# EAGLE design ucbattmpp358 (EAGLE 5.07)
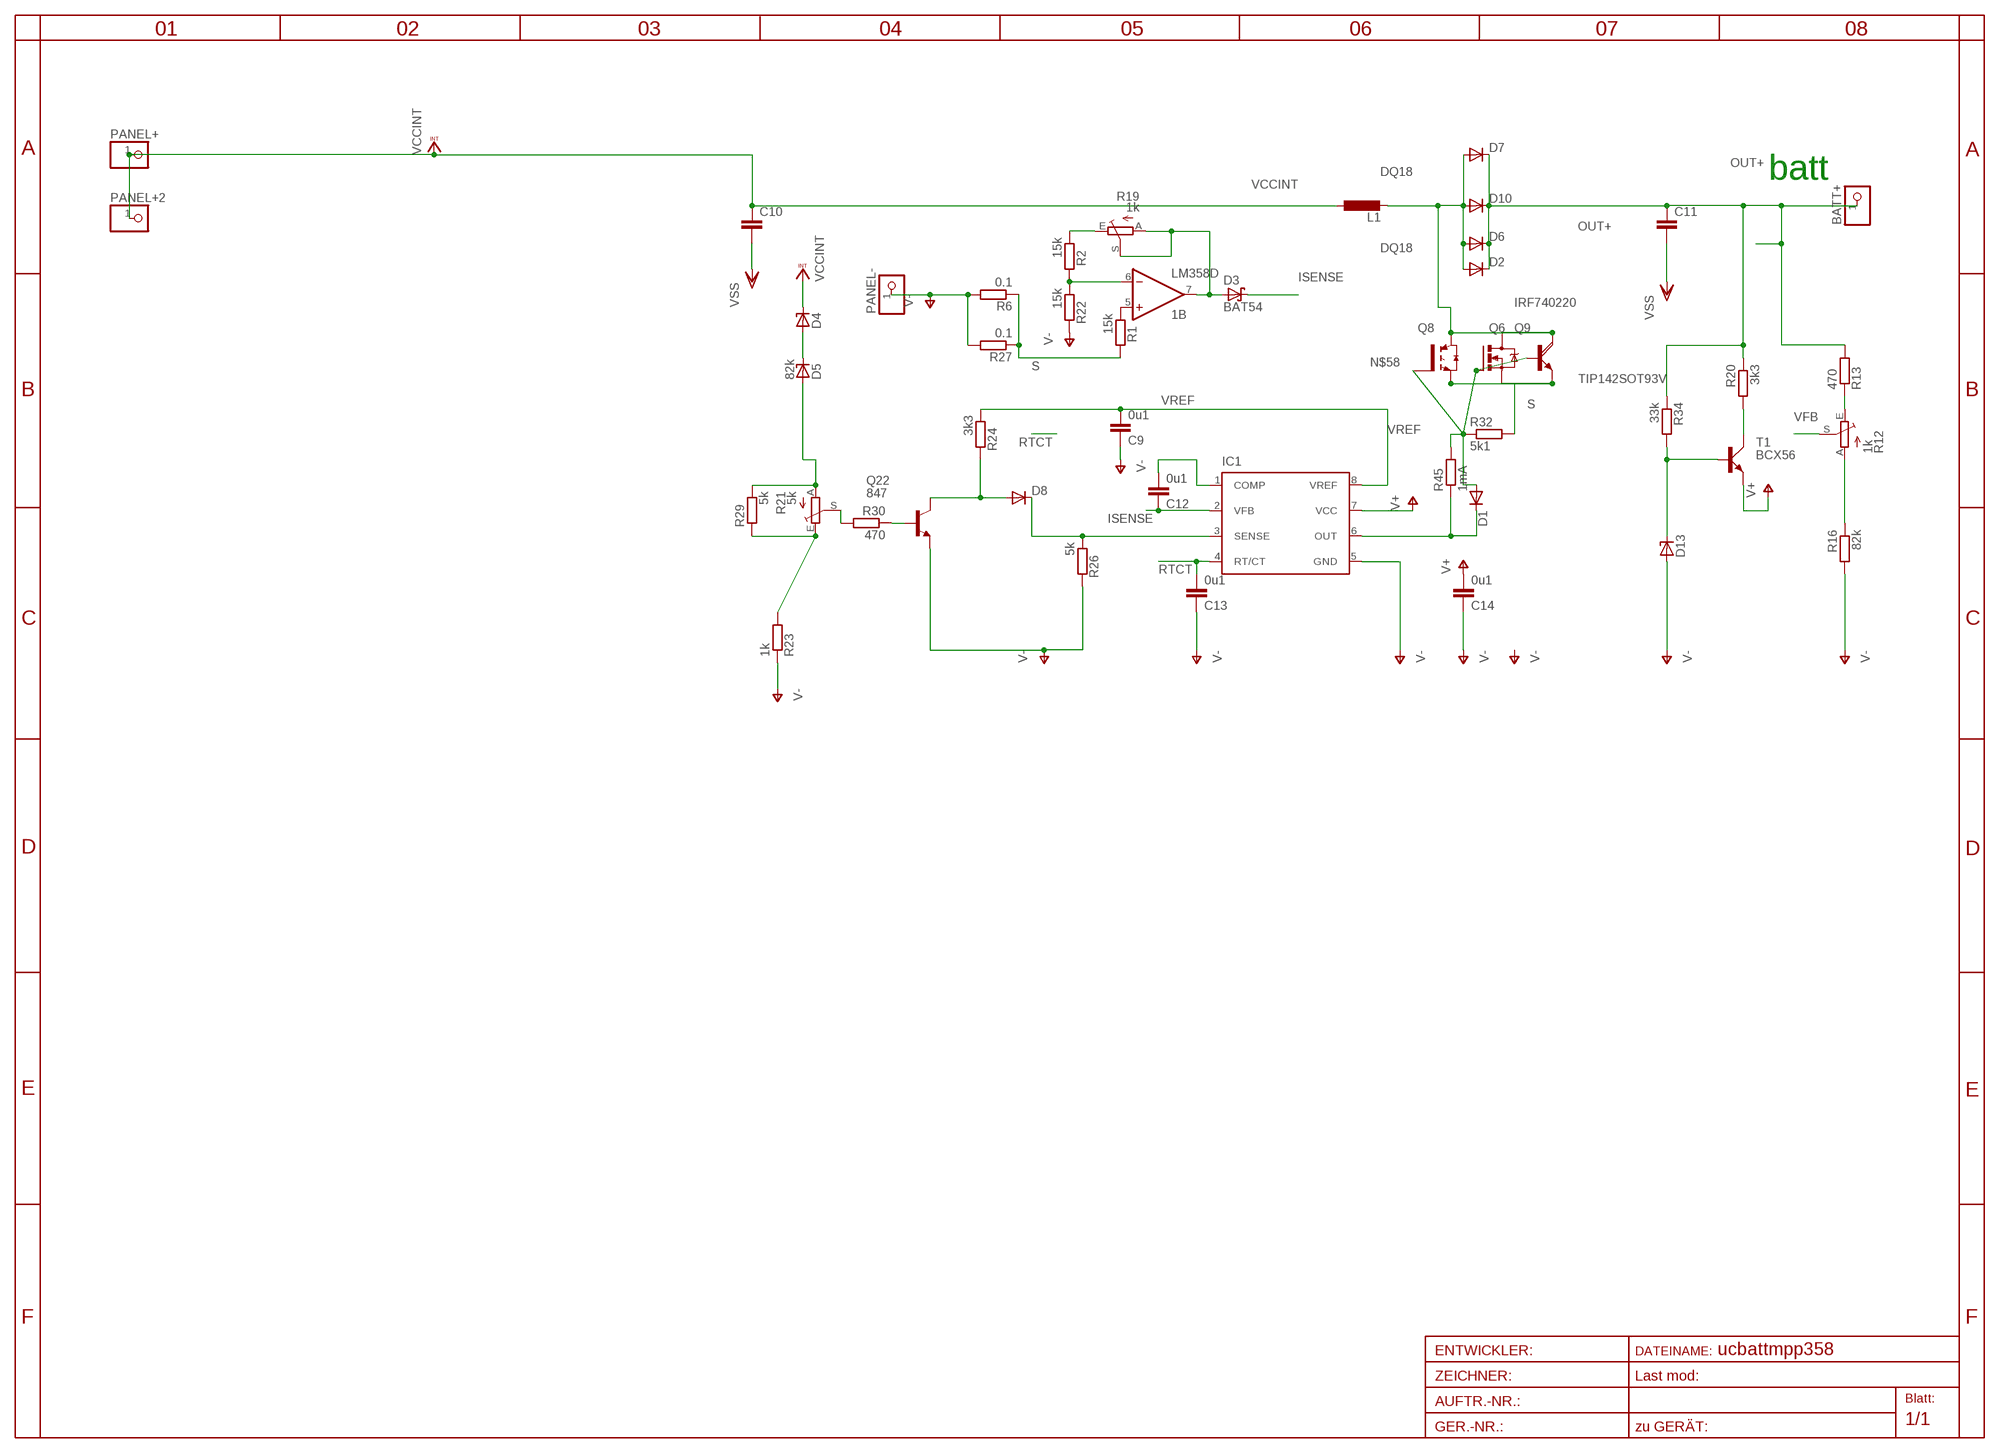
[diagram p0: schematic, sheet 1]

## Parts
1  LM358D  [SO08]
BATT+  PINHD-1X12MM3  [1X2MM3]
C9  0u1  C-EUC1206  [C1206]
C10  C-EU075-052X106  [C075-052X106]
C11  C-EU075-052X106  [C075-052X106]
C12  0u1  C-EUC0805  [C0805]
C13  0u1  C-EUC1206  [C1206]
C14  0u1  C-EUC1206  [C1206]
D1  DIODE-MINIMELF  [MINIMELF]
D2  DIODE-SMC  [SMC]
D3  BAT54  [SOT23]
D4  ZENER-DIODESOD80C  [SOD80C]
D5  82k  ZENER-DIODESOD80C  [SOD80C]
D6  DIODE-SMC  [SMC]
D7  DIODE-SMC  [SMC]
D8  DIODE-MINIMELF  [MINIMELF]
D10  DIODE-SMC  [SMC]
D13  ZENER-DIODESOD80C  [SOD80C]
IC1  UC1843D8  [SO-08]
L1  L-EUOPEN6  [OPEN6_3]
PANEL+  PINHD-1X11MM6  [1X1MM8]
PANEL+2  PINHD-1X12MM3  [1X2MM3]
PANEL-  PINHD-1X12MM3  [1X2MM3]
Q6  IRF740220  [TO220BV]
Q8  IRG4BC15UD-S  [D2PACK]
Q9  TIP142SOT93V  [SOT93V]
Q22  847  BC847ASMD  [SOT23]
R1  15k  R-EU_R0805  [R0805]
R2  15k  R-EU_R0805  [R0805]
R6  0.1  R-EU_0207/10  [0207/10]
R12  1k  TRIM_EU-S64W  [S64W]
R13  470  R-EU_R0805  [R0805]
R16  82k  R-EU_R0805  [R0805]
R19  1k  TRIM_EU-S64W  [S64W]
R20  3k3  R-EU_R0805  [R0805]
R21  5k  TRIM_EU-S64W  [S64W]
R22  15k  R-EU_R0805  [R0805]
R23  1k  R-EU_R0805  [R0805]
R24  3k3  R-EU_R0805  [R0805]
R26  5k  R-EU_R0805  [R0805]
R27  0.1  R-EU_R3216  [R3216]
R29  5k  R-EU_R0805  [R0805]
R30  470  R-EU_R0805  [R0805]
R32  5k1  R-EU_R0805  [R0805]
R34  33k  R-EU_R0805  [R0805]
R45  1mA  R-EU_R0805  [R0805]
T1  BCX56  [SOT223]

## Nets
DQ18: D2.A D6.A D7.A D10.A L1.2 Q6.D Q8.2(C) Q9.C
ISENSE: D3.3(C) D8.C IC1.3(SENSE) R26.1
N$1: 1.5(B:+IN) R1.1
N$2: R2.1 R19.E
N$3: Q22.1(B) R30.1
N$18: C12.2 IC1.1(COMP)
N$21: R12.A R16.1
N$22: 1.7(B:OUT) D3.1(A) R19.A R19.S
N$23: R20.2 T1.2(C)
N$25: D1.C IC1.6(OUT) R45.1
N$26: D13.C R34.2 T1.1(B)
N$27: 1.6(B:-IN) R2.2 R22.1
N$30: D4.A D5.C
N$32: D5.A R21.A R29.1
N$34: R21.E R23.2 R29.2
N$37: R12.E R13.1
N$58: D1.A Q6.G Q8.1(G) Q9.B R32.1 R45.2
N$71: D8.A Q22.3(C) R24.2
OUT+: BATT+.1 C11.1 D2.C D6.C D7.C D10.C R13.2 R20.1 R34.1
PRB1: R21.S R30.2
RTCT: C13.2 IC1.4(RT/CT)
S: Q6.S Q8.3(E) Q9.E R1.2 R6.1 R27.1 R32.2
V+: C14.2 IC1.7(VCC) T1.3(E)
V-: C9.1 C10.2 C11.2 C13.1 C14.1 D13.A IC1.5(GND) PANEL-.1 Q22.2(E) R6.2 R16.2 R22.2 R23.1 R26.2 R27.2 ; supply symbol labelled VSS
VCCINT: C10.1 D4.C L1.1 PANEL+2.1 PANEL+.1
VFB: C12.1 IC1.2(VFB) R12.S
VREF: C9.2 IC1.8(VREF) R24.1
Unconnected: 1.1(A:OUT) 1.2(A:-IN) 1.3(A:+IN)

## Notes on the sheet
- batt

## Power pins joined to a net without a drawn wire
V+: 1.8(P:V+)
V-: 1.4(P:V-)

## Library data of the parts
1 = linear:LM358: OP AMP also LM158; LM258; LM2904 Source: http://cache.national.com/ds/LM/LM158.pdf
BATT+ PANEL+ PANEL+2 PANEL- = pinhead:PINHD-1X1: PIN HEADER
C9-C14 = rcl:C-EU: CAPACITOR, European symbol
D1 D2 D6-D8 D10 = diode:DIODE-: DIODE
D3 = diode:BAT54: Schottky Diodes
D4 D5 D13 = diode:ZENER-DIODE: Z-Diode
IC1 = texas:UC1843D8: PULSE WIDTH MODULATOR
L1 = rcl:L-EU: INDUCTOR, European symbol
Q6 = transistor-power:IRF740: N-CHANNEL MOS FET
Q8 = transistor-power:IRG4BC15UD-: INSULATED GATE BIPOLAR TRANSISTOR WITH ULTRAFAST SOFT RECOVERY DIODE
Q9 = transistor-power:TIP142: NPN DARLINGTON TRANSISTOR
Q22 = transistor-npn:BC847*: NPN Transistor
R1 R2 R6 R13 R16 R20 R22-R24 R26 R27 R29 R30 R34 = rcl:R-EU_: RESISTOR, European symbol
R12 R19 R21 = pot:TRIM_EU-: POTENTIOMETER
R32 R45 = rcl-2:R-EU_: RESISTOR, European symbol
T1 = transistor-power:BCX56

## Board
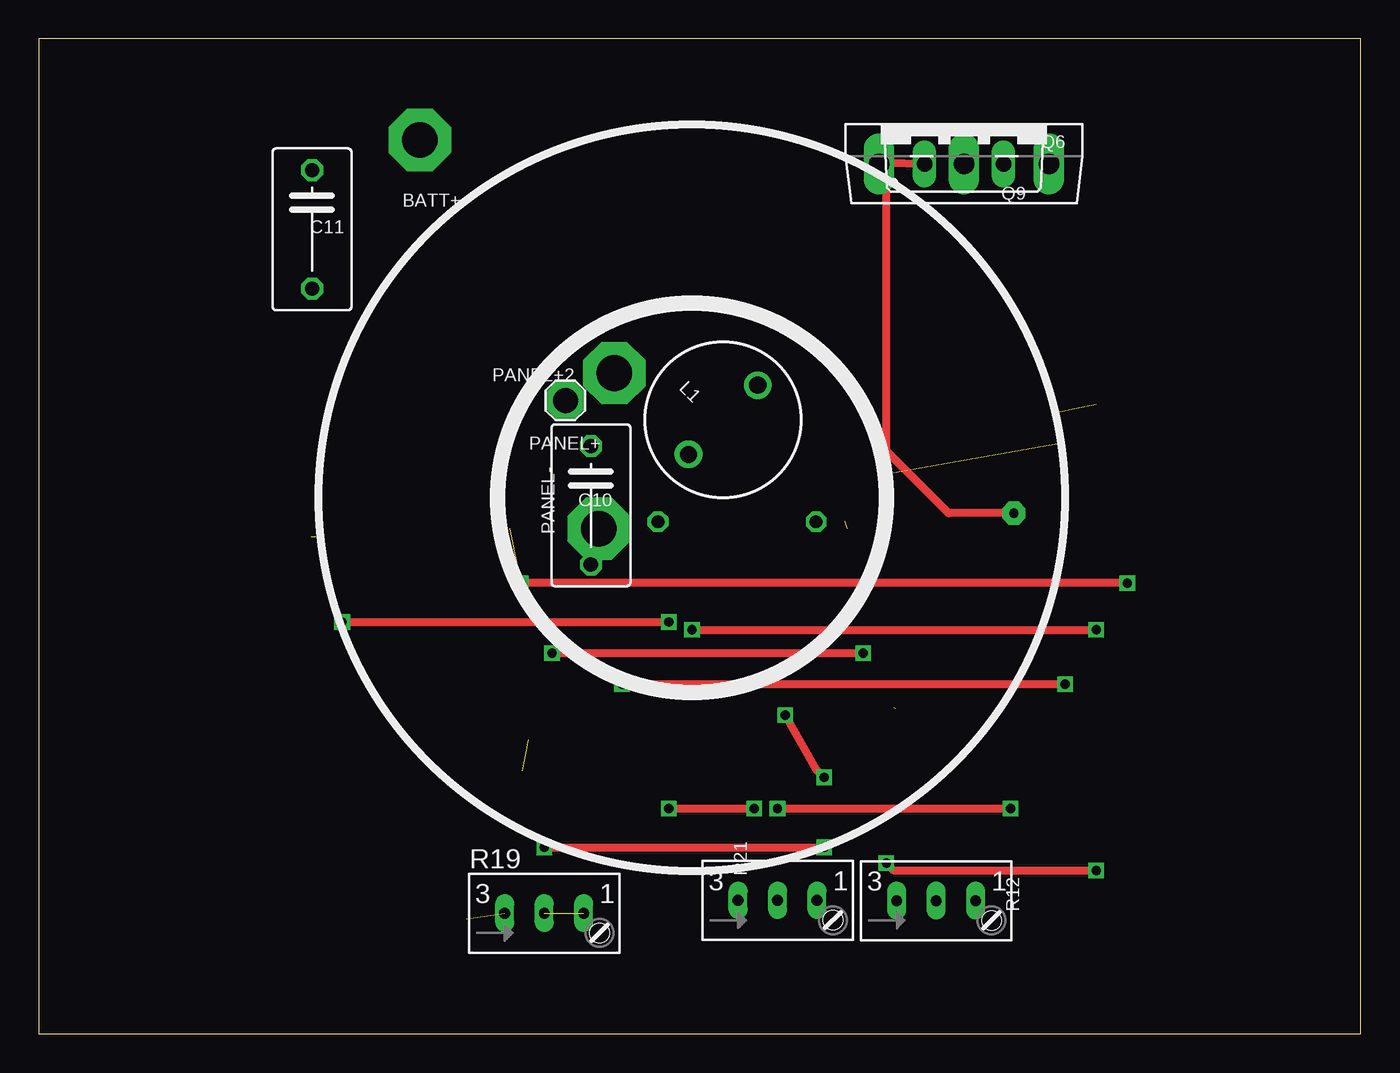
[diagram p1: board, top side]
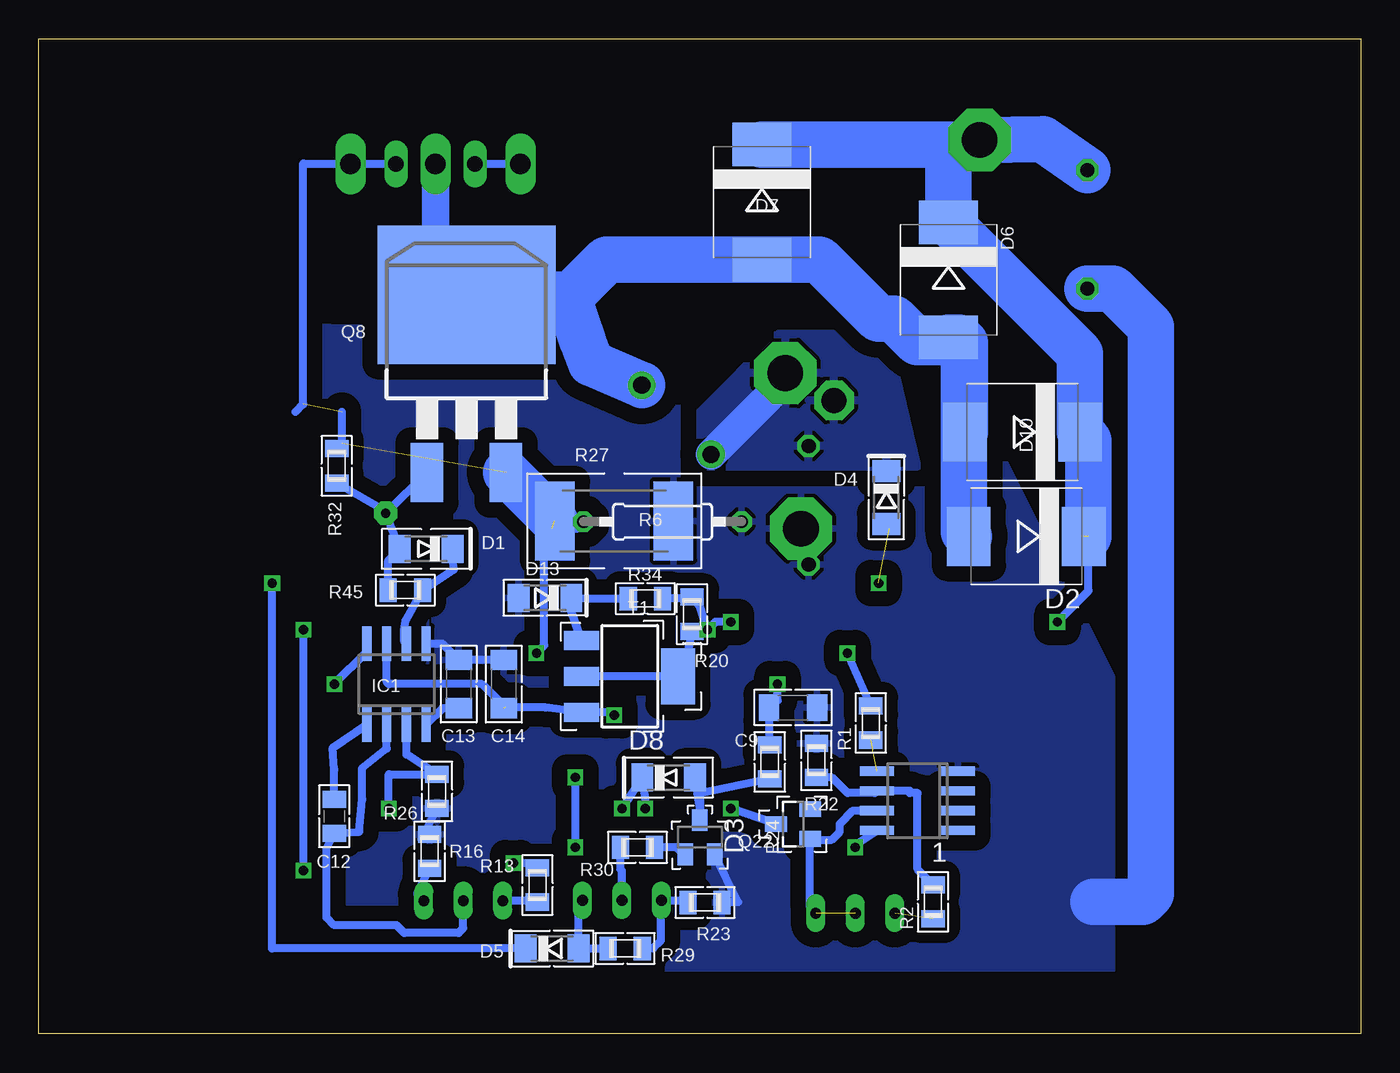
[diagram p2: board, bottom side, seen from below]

Size 85 x 64 mm. Coordinates in mm from the lower left corner, seen from the top.
Outline: 0,0 85,0 85,64 0,64 0,0
Copper layers (1*16): Top 0.035mm / dielectric 1.5mm / Bottom 0.035mm
Design rules "default *": minimum track width 10mil, minimum drill 24mil, track to track 8mil, track to pad 8mil, pad to pad 8mil, via to via 8mil, smd to smd 8mil, copper to edge 4mm, drill to drill 8mil, minimum pad ring 10mil, minimum via ring 8mil, stop-mask expansion 4mil, vias tented up to drill 0mil, thermal gap 10mil

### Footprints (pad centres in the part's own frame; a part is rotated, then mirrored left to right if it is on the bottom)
SO08 = smd 0.6 x 2.2: 1 -1.905,-2.6; 2 -0.635,-2.6; 3 0.635,-2.6; 4 1.905,-2.6; 5 1.905,2.6; 6 0.635,2.6; 7 -0.635,2.6; 8 -1.905,2.6
1X2MM3 = drill 2.3 pad 4 octagon: 1 0,0
C1206 = smd 1.3 x 1.7: 1 -1.55,0; 2 1.55,0
C075-052X106 = drill 0.914 octagon: 1 -3.81,0; 2 3.81,0
C0805 = smd 1.1 x 1.5: 1 -1.1,0; 2 1.1,0
MINIMELF = smd 1.4 x 1.8: A 1.7,0; C -1.7,0
SMC = smd 2.8 x 3.8: A 3.7,0; C -3.7,0
SOT23 = smd 1 x 1.4: 1 -0.95,-1.1; 2 0.95,-1.1; 3 0,1.1
SOD80C = smd 1.4 x 1.8: A 1.7,0; C -1.7,0
SO-08 = smd 0.6 x 2.2: 1 -1.905,-2.6; 2 -0.635,-2.6; 3 0.635,-2.6; 4 1.905,-2.6; 5 1.905,2.6; 6 0.635,2.6; 7 -0.635,2.6; 8 -1.905,2.6
OPEN6_3 = drill 1.1 pad 1.778 round: 1 -3.15,0; 2 3.15,0
1X1MM8 = drill 1.6 pad 2.54 octagon: 1 0,0
TO220BV = drill 1.016 long: D 0,-2.54; G -2.54,-2.54; S 2.54,-2.54
D2PACK = smd 2.083 x 3.81: 1 -2.54,-8.89; 3 2.54,-8.89 | smd 11.43 x 8.89: 2 0,2.54
SOT93V = drill 1.3 pad 1.676 long: B -5.461,-2.54; C 0,-2.54; E 5.461,-2.54
R0805 = smd 1.1 x 1.5: 1 -1.1,0; 2 1.1,0
0207/10 = drill 0.813 octagon: 1 -5.08,0; 2 5.08,0
S64W = drill 0.7 long: A 2.54,1.27; E -2.54,1.27; S 0,1.27
R3216 = smd 2.54 x 5.08: 1 -3.81,0; 2 3.81,0
SOT223 = smd 1.219 x 2.235: 1 -2.311,-3.099; 2 0,-3.099; 3 2.311,-3.099 | smd 3.6 x 2.2: 4 0,3.099

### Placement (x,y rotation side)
1  28.5,15 90 bottom
BATT+  24.5,57.5 0 top
C9  36.5,21 180 bottom
C10  35.5,34 270 top
C11  17.57,51.75 270 top
C12  66,14 90 bottom
C13  58,22.5 270 bottom
C14  55.1,22.5 270 bottom
D1  60.1,31.2 180 bottom
D2  21.5,32 180 bottom
D3  36.5,13.5 90 bottom
D4  30.5,34.5 270 bottom
D5  52,5.5 0 bottom
D6  26.5,48.5 270 bottom
D7  38.5,53.5 270 bottom
D8  44.5,16.5 0 bottom
D10  21.75,38.71 180 bottom
D13  52.46,28.05 180 bottom
IC1  62,22.5 0 bottom
L1  44,39.5 45 top
PANEL+  33.86,40.74 0 top
PANEL+2  37,42.5 0 top
PANEL-  36,32.5 90 top
Q6  59.5,58.5 0 top
Q8  57.5,45 0 bottom
Q9  59.5,58.5 0 top
Q22  42.49,12.66 0 bottom
R1  31.5,20 90 bottom
R2  27.5,8.5 90 bottom
R6  44.9,32.95 0 bottom
R12  57.7,7.3 0 top
R13  52.94,9.58 90 bottom
R16  59.88,11.75 90 bottom
R19  32.5,6.5 0 top
R20  43,27 270 bottom
R21  47.51,7.32 0 top
R22  35,17.6 90 bottom
R23  42.16,8.46 180 bottom
R24  38,17.5 270 bottom
R26  59.4,15.6 270 bottom
R27  48,33 0 bottom
R29  47.3,5.5 0 bottom
R30  46.5,12 180 bottom
R32  65.84,36.55 90 bottom
R34  46,28 180 bottom
R45  61.43,28.55 180 bottom
T1  47,23 270 bottom

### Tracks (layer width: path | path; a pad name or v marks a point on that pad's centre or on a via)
DQ18
  Bottom 1.778: 59.5,48.04 Q9.C
  Bottom 2.54: Q8.2 59.5,48.04
  Bottom 3: Q8.2 51.04,47.54 50.97,47.34 | 50.97,47.34 50,44.5 49.5,43.15 L1.2 | 50.97,47.34 48.51,49.8 D7.A 34.8,49.8 31,46 30,46 28.5,44.5 26.8,44.5 D6.A 25.8,44.8 25.5,44.5 | 25.5,44.5 25.5,32.3 D2.A | D10.A 25.45,44.45 25.5,44.5
ISENSE  (via drill 0.6)
  Top 0.5: v47.5,14.5 v62.5,14.5 | v40.5,14.5 v46,14.5
  Bottom 0.5: IC1.3 61.37,17.96 R26.1 62.5,16.7 v62.5,14.5 | v47.5,14.5 D8.C 46,15.2 v46,14.5 | D3.3 v40.5,14.5
N$1  (1 unrouted)
N$2  (1 unrouted)
N$3
  Bottom 0.5: Q22.1 43.56,11.56 44,12 R30.1
N$18
  Bottom 0.5: IC1.1 66.1,18.4 66,17 C12.2
N$21
  Bottom 0.5: R12.A 60.67,9.01 R16.1
N$22  (1 unrouted)
  Bottom 0.5: R19.A 35.4,8.13 D3.1 35.35,12.5 34,12.5 33.5,13 33.5,13.5 32.63,14.37 1.7
N$23
  Bottom 0.5: T1.2 43.6,23 R20.2
N$25
  Bottom 0.5: IC1.6 61.5,25.23 61.5,26 61.43,26.57 R45.1 58.33,29.87 D1.C
N$26
  Bottom 0.5: R34.2 49.71,28 D13.C 50.76,27.15 T1.1
N$27
  Bottom 0.5: R2.2 28.5,10.6 28.5,15.5 29,15.5 29,15.63 1.6 31.23,15.5 33,15.5 34,16.5 R22.1
N$30  (via drill 0.6)  (1 unrouted)
  Top 0.5: v70,29 v31,29
  Bottom 0.5: D5.C 70,5.5 v70,29 | 30.3,32.5 D4.A
N$32
  Bottom 0.5: R29.1 D5.A 50.3,8.34 R21.A
N$34
  Bottom 0.5: R29.2 45.5,5.5 45,6 45,8.56 R21.E 43.4,8.59 R23.2
N$37
  Bottom 0.5: R13.1 53.03,8.57 R12.E
N$58  (via drill 0.6 pad 1.5)
  Top 0.5: Q6.G 54.46,56.04 54.5,53 54.5,37.5 58.5,33.5 v62.7,33.5
  Bottom 0.5: 62.59,33.55 R32.1 | 62.59,33.55 Q8.1 | Q6.G Q9.B | R45.2 62.53,30.43 D1.A v62.7,33.5 62.7,33.95 62.59,33.55
N$71
  Bottom 0.5: 42.49,14.5 Q22.3 | 42.49,14.5 42.49,15.46 R24.2 | 42.49,14.5 D8.A
OUT+  (via drill 0.6)  (1 unrouted)
  Top 0.5: v42,26 v68,26 | v68,10.5 55,10.5 v54.5,11 | v19.5,26.5 v40.5,26.5
  Bottom 0.5: R34.1 43,28 R20.1 42.5,27.5 v42,26 41.5,26.5 v40.5,26.5 | v68,26 v68,10.5 | v54.5,11 53.26,11 R13.2 | 17.5,32 17.5,28.5 v19.5,26.5
  Bottom 3: C11.1 20.44,57.56 BATT+.1 24.8,57.2 26.5,57.2 | 17.5,32 17.5,38.16 D10.C 18.05,43.75 D6.C 26.5,57.2 | 26.5,57.2 D7.C
PRB1
  Bottom 0.5: R30.2 47.6,10.6 47.5,10.5 R21.S
RTCT
  Bottom 0.5: IC1.4 59.05,20.95 C13.2
S  (via drill 0.6)  (3 unrouted)
  Top 0.5: v33,24.5 v53,24.5
  Bottom 0.5: Q6.S Q9.E 67.96,55.96 68,56 68,40.5 68.5,40 | R32.2 65.5,37.98 65.5,40 | R1.2 v33,24.5 | v53,24.5 52.5,25 52.5,32 52,32.5 50.42,32.5 R6.1
  Bottom 3: R27.1 51.85,33 Q8.3
V+  (via drill 0.6)  (1 unrouted)
  Top 0.5: v32.5,12 v50.5,12 | v48,20.5 50,17 v50.5,16.5
  Bottom 0.5: 1.8 32.6,12.1 v32.5,12 | v48,20.5 48.19,20.69 T1.3 52.41,21 55,21 56.5,22.5 62.5,22.5 62.63,22.64 IC1.7 | v50.5,12 v50.5,16.5
V-
  Bottom 0.5: C14.1 C13.1 59.05,25.1 IC1.5 | R16.2 60.4,12.53 R26.2 | R23.1 40.04,8.47 Q22.2
  Bottom 3: C11.2 15.94,47.94 13.5,45.5 13.5,9 14,8.5 17.19,8.5
  pour Bottom (isolate 1, rank 4): 68.5,1 16,1 16,23 27,45 69,45.5
VCCINT
  Bottom 2: L1.1 37,42.05
  Bottom 3: 37,42.05 PANEL+2.1
  pour Bottom (isolate 1): 30.5,45 37.5,45 42.5,40 42.5,36.5 28.5,36.5
VFB
  Bottom 0.5: IC1.2 62.63,18.36 64.2,17.1 64.2,15.1 64.4,13 C12.1 66.5,11.9 66.5,7.5 66,7 62,7 61.5,6.5 58,6.5 57.7,6.79 R12.S
VREF  (via drill 0.6)
  Top 0.5: v37.5,22.5 v66,22.5
  Bottom 0.5: R24.1 C9.2 37.5,21.45 v37.5,22.5 | IC1.8 63.91,24.59 v66,22.5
